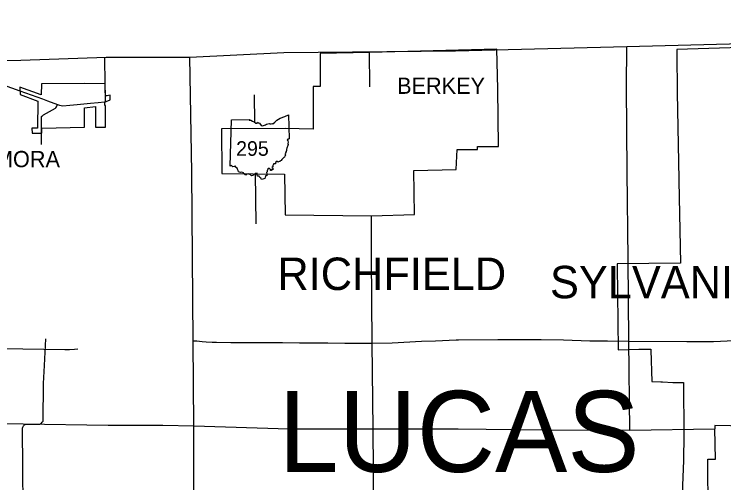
# Model space of a CAD drawing. Extents: x -232 to 448, y 619 to 1059.
# Drawn here: x 68.14 to 113.08, y 930.02 to 959.66 of the extents above; entities that cross this region are included whole.
import ezdxf

# ---------------------------------------------------------------- set-up
doc = ezdxf.new("R2010")
doc.units = 0
doc.layers.add('Default', color=7, linetype='Continuous')

msp = doc.modelspace()

# ---------------------------------------------------------------- linework, layer by layer
at = {"layer": 'Default'}
for p, q in [((73.282, 953.819), (73.282, 952.514)), ((73.923, 953.889), (73.89, 953.883)), ((73.923, 952.514), (73.923, 953.889)), ((81.816, 950.052), (81.898, 952.981)), ((81.816, 950.052), (81.898, 952.981)), ((73.282, 952.514), (73.923, 952.514))]:
    msp.add_line(p, q, dxfattribs=at)
for points in [[(191.559, 959.664), (178.631, 959.398), (164.124, 958.912), (149.104, 958.636), (143.624, 958.482), (132.12, 958.132), (126.614, 958.11), (126.592, 958.099), (122.234, 957.803), (110.103, 957.439)], [(106.941, 957.63), (115.861, 957.858), (129.538, 958.269), (129.538, 958.269), (133.907, 958.565), (133.928, 958.575), (139.422, 958.598), (145.054, 958.769)], [(79.258, 956.939), (85.208, 957.249), (96.085, 957.352), (106.941, 957.63)], [(107.118, 933.356), (107.061, 939.005), (107.011, 944.176), (106.952, 949.683), (106.905, 955.068), (106.941, 957.63)], [(87.519, 957.171), (87.518, 955.095), (87.079, 955.095), (87.068, 952.399), (85.299, 952.427), (81.27, 952.42), (81.281, 949.595), (85.266, 949.55)], [(85.303, 946.964), (90.762, 946.914), (93.491, 946.996), (93.446, 949.768), (96.124, 949.84), (96.195, 951.099), (97.484, 951.096), (97.481, 951.285), (98.815, 951.296), (98.758, 954.95), (98.7, 957.442)], [(98.7, 957.442), (90.638, 957.247), (87.519, 957.171)], [(90.668, 955.071), (90.643, 957.3)], [(110.103, 957.439), (110.104, 957.227), (110.119, 954.681)], [(46.162, 956.25), (63.186, 956.696), (68.56, 956.753), (73.967, 956.956), (79.258, 956.939)], [(73.906, 955.226), (73.886, 956.954)], [(79.515, 933.612), (79.396, 949.665), (79.258, 956.939)], [(63.784, 955.175), (63.883, 955.199), (64.007, 955.218), (64.652, 955.27), (64.823, 955.279), (65.934, 955.264), (67.19, 955.243), (67.317, 955.229), (67.375, 955.221), (67.444, 955.198), (68.507, 954.806)], [(72.566, 955.275), (69.862, 955.256), (69.851, 954.569), (68.505, 955.049)], [(68.505, 955.049), (68.508, 954.581)], [(73.884, 954.112), (73.916, 954.115), (73.969, 954.141), (74.221, 954.251), (74.224, 954.541), (74.122, 954.518), (74.02, 954.496), (73.913, 954.493), (73.906, 955.264), (72.566, 955.275)], [(73.913, 954.448), (73.91, 954.903), (73.906, 955.226)], [(68.507, 954.806), (69.922, 954.3)], [(68.508, 954.581), (69.627, 954.172), (69.622, 952.453), (69.265, 952.458), (69.271, 952.144), (69.896, 952.148), (69.891, 952.455)], [(83.387, 952.814), (83.367, 954.554)], [(110.119, 954.681), (110.225, 949.22), (110.228, 949.123), (110.343, 943.922)], [(69.922, 954.3), (70.256, 954.181), (70.882, 953.951)], [(71.661, 953.911), (72.123, 953.946), (72.973, 954.026)], [(72.973, 954.026), (73.456, 954.071), (73.863, 954.11)], [(73.863, 954.11), (73.916, 954.115), (73.913, 954.448)], [(73.89, 953.883), (73.884, 954.112)], [(69.891, 952.455), (72.584, 952.515), (72.6, 953.748), (73.282, 953.819)], [(69.898, 953.214), (69.902, 953.218), (69.989, 953.289), (70.755, 953.728), (70.786, 953.748), (70.812, 953.799), (70.882, 953.951)], [(70.882, 953.951), (71.013, 953.906), (71.119, 953.878), (71.23, 953.877), (71.661, 953.911)], [(69.875, 952.453), (69.873, 953.188), (69.898, 953.214)], [(81.898, 952.981), (83.035, 953), (83.017, 952.965), (83.124, 952.957), (83.238, 952.895), (83.335, 952.855), (83.452, 952.762), (83.523, 952.763), (83.553, 952.839), (83.607, 952.781), (83.671, 952.77), (83.782, 952.63), (83.873, 952.599), (83.983, 952.648), (84.064, 952.655), (84.124, 952.703), (84.28, 952.744), (84.324, 952.719), (84.406, 952.724), (84.448, 952.742), (84.52, 952.726), (84.647, 952.833), (84.777, 952.958), (84.978, 953.077), (85.278, 953.189), (85.515, 953.289), (85.549, 951.769)], [(81.898, 952.981), (83.035, 953), (83.017, 952.965), (83.124, 952.957), (83.238, 952.895), (83.335, 952.855), (83.452, 952.762), (83.523, 952.763), (83.553, 952.839), (83.607, 952.781), (83.671, 952.77), (83.782, 952.63), (83.873, 952.599), (83.983, 952.648), (84.064, 952.655), (84.124, 952.703), (84.28, 952.744), (84.324, 952.719), (84.406, 952.724), (84.448, 952.742), (84.52, 952.726), (84.647, 952.833), (84.777, 952.958), (84.978, 953.077), (85.278, 953.189), (85.515, 953.289), (85.549, 951.769)], [(69.878, 951.41), (69.875, 952.453)], [(85.549, 951.769), (85.514, 951.748), (85.459, 951.758), (85.423, 951.715), (85.468, 951.644), (85.489, 951.569), (85.47, 951.486), (85.489, 951.418), (85.476, 951.361), (85.442, 951.304), (85.43, 951.25), (85.401, 951.192), (85.404, 951.16), (85.376, 951.135), (85.381, 951.04), (85.367, 950.987), (85.372, 950.942), (85.327, 950.93), (85.337, 950.892), (85.309, 950.863), (85.315, 950.814), (85.282, 950.782), (85.314, 950.718), (85.288, 950.698), (85.267, 950.62), (85.21, 950.604), (85.094, 950.463), (85.053, 950.409), (85.007, 950.396), (84.982, 950.341), (84.926, 950.34), (84.841, 950.302), (84.785, 950.368), (84.689, 950.289), (84.677, 950.197), (84.555, 950.2), (84.56, 950.154), (84.533, 950.141), (84.508, 950.095), (84.522, 950.012), (84.465, 949.991), (84.472, 949.944), (84.509, 949.914), (84.525, 949.823), (84.464, 949.842), (84.414, 949.765), (84.363, 949.783), (84.38, 949.848), (84.293, 949.926), (84.211, 949.864), (84.169, 949.763), (84.168, 949.696), (84.107, 949.655), (84.146, 949.56), (84.139, 949.494), (84.14, 949.432), (84.064, 949.434), (84.018, 949.266)], [(85.549, 951.769), (85.514, 951.748), (85.459, 951.758), (85.423, 951.715), (85.468, 951.644), (85.489, 951.569), (85.47, 951.486), (85.489, 951.418), (85.476, 951.361), (85.442, 951.304), (85.43, 951.25), (85.401, 951.192), (85.404, 951.16), (85.376, 951.135), (85.381, 951.04), (85.367, 950.987), (85.372, 950.942), (85.327, 950.93), (85.337, 950.892), (85.309, 950.863), (85.315, 950.814), (85.282, 950.782), (85.314, 950.718), (85.288, 950.698), (85.267, 950.62), (85.21, 950.604), (85.094, 950.463), (85.053, 950.409), (85.007, 950.396), (84.982, 950.341), (84.926, 950.34), (84.841, 950.302), (84.785, 950.368), (84.689, 950.289), (84.677, 950.197), (84.555, 950.2), (84.56, 950.154), (84.533, 950.141), (84.508, 950.095), (84.522, 950.012), (84.465, 949.991), (84.472, 949.944), (84.509, 949.914), (84.525, 949.823), (84.464, 949.842), (84.414, 949.765), (84.363, 949.783), (84.38, 949.848), (84.293, 949.926), (84.211, 949.864), (84.169, 949.763), (84.168, 949.696), (84.107, 949.655), (84.146, 949.56), (84.139, 949.494), (84.14, 949.432), (84.064, 949.434), (84.018, 949.266)], [(84.018, 949.266), (83.885, 949.234), (83.793, 949.215), (83.761, 949.291), (83.695, 949.331), (83.652, 949.408), (83.557, 949.419), (83.535, 949.524), (83.524, 949.61), (83.395, 949.589), (83.36, 949.537), (83.314, 949.522), (83.287, 949.47), (83.225, 949.465), (83.158, 949.44), (83.114, 949.492), (83.004, 949.544), (82.955, 949.571), (82.851, 949.529), (82.829, 949.48), (82.747, 949.502), (82.728, 949.557), (82.678, 949.573), (82.667, 949.632), (82.561, 949.663), (82.479, 949.65), (82.336, 949.697), (82.327, 949.774), (82.278, 949.867), (82.253, 949.932), (82.162, 949.982), (82.144, 950.059), (82.115, 950.057), (82.088, 950.026), (81.988, 950.011), (81.947, 950.043), (81.891, 950.097), (81.816, 950.052)], [(84.018, 949.266), (83.885, 949.234), (83.793, 949.215), (83.761, 949.291), (83.695, 949.331), (83.652, 949.408), (83.557, 949.419), (83.535, 949.524), (83.524, 949.61), (83.395, 949.589), (83.36, 949.537), (83.314, 949.522), (83.287, 949.47), (83.225, 949.465), (83.158, 949.44), (83.114, 949.492), (83.004, 949.544), (82.955, 949.571), (82.851, 949.529), (82.829, 949.48), (82.747, 949.502), (82.728, 949.557), (82.678, 949.573), (82.667, 949.632), (82.561, 949.663), (82.479, 949.65), (82.336, 949.697), (82.327, 949.774), (82.278, 949.867), (82.253, 949.932), (82.162, 949.982), (82.144, 950.059), (82.115, 950.057), (82.088, 950.026), (81.988, 950.011), (81.947, 950.043), (81.891, 950.097), (81.816, 950.052)], [(83.46, 946.397), (83.424, 949.594)], [(85.266, 949.55), (85.303, 946.964)], [(90.764, 944.294), (90.762, 946.914)], [(90.991, 918.82), (91.015, 921.24), (90.986, 922.812), (90.909, 928.215), (90.864, 933.426), (90.807, 938.842), (90.764, 944.289), (90.764, 944.294)], [(110.343, 943.922), (106.33, 943.872)], [(106.33, 943.872), (106.333, 943.754), (106.389, 938.428)], [(68.668, 933.34), (68.667, 933.469), (68.686, 933.538), (68.737, 933.623), (68.791, 933.681), (68.88, 933.732), (69.755, 933.736), (69.842, 933.771), (69.921, 933.842), (69.972, 933.917), (70, 936.289), (70.052, 937.429), (70.142, 939.131)], [(79.475, 939.007), (79.713, 939.003), (80.049, 938.963), (80.292, 938.945), (80.671, 938.923), (80.943, 938.914), (81.864, 938.902), (82.238, 938.897), (83.484, 938.885), (83.757, 938.883), (84.895, 938.887), (85.12, 938.886), (86.203, 938.869), (86.464, 938.864), (87.764, 938.864), (87.996, 938.863), (89.08, 938.855), (89.369, 938.853), (89.64, 938.851), (89.914, 938.849), (90.619, 938.843), (90.807, 938.842), (92.079, 938.882), (93.93, 938.973), (94.825, 938.997), (96.122, 939.061), (96.269, 939.063)], [(96.269, 939.063), (98.756, 939.086), (100.61, 939.082), (101.512, 939.078), (102.932, 939.054), (104.596, 939.009), (105.449, 939.008), (105.719, 938.998), (107.059, 938.985), (110.73, 938.963), (112.415, 938.958), (113.741, 939.018), (113.85, 939.02)], [(47.839, 938.562), (48.772, 938.567), (49.15, 938.57), (50.258, 938.584), (51.875, 938.577), (53.435, 938.615), (54.613, 938.651), (55.518, 938.656), (55.721, 938.688), (56.005, 938.698), (57.276, 938.676), (57.825, 938.671), (59.47, 938.649), (60.673, 938.643), (62.841, 938.614), (63.431, 938.604), (65.59, 938.555), (68.68, 938.499), (71.353, 938.44), (71.641, 938.442), (71.959, 938.47), (72.174, 938.49)], [(106.389, 938.428), (107.689, 938.467), (107.715, 938.467), (107.797, 938.469), (108.339, 938.479), (108.357, 938.48), (108.454, 938.474)], [(108.454, 938.474), (108.456, 938.41), (108.521, 936.418)], [(108.521, 936.418), (109.098, 936.402), (109.19, 936.399), (109.839, 936.369), (109.901, 936.366), (110.49, 936.362), (110.522, 936.362)], [(110.522, 936.362), (110.545, 933.036), (110.544, 932.963), (110.523, 931.501), (110.519, 931.425), (110.286, 925.582)], [(131.674, 934.149), (123.263, 933.603), (115.502, 933.584), (112.51, 933.646), (112.513, 933.427)], [(46.355, 933.706), (52.547, 933.741), (63.267, 933.761), (68.715, 933.752), (74.09, 933.66), (77.553, 933.663), (79.515, 933.612)], [(68.719, 922.826), (68.719, 924.637), (68.714, 927.231), (68.699, 928.352), (68.678, 931.091), (68.668, 933.34)], [(79.52, 926.921), (79.515, 933.612)], [(79.515, 933.612), (85.524, 933.441), (90.871, 933.431), (96.246, 933.427), (101.567, 933.359), (107.118, 933.356)], [(107.118, 933.356), (112.513, 933.427)], [(112.057, 920.929), (112.055, 922.696), (112.064, 926.015), (112.087, 928.105), (112.069, 931.513), (112.553, 931.512), (112.513, 933.427)]]:
    msp.add_lwpolyline(points, dxfattribs=at)

# ---------------------------------------------------------------- texts
for s, height, p in [('BERKEY', 1.026, (92.388, 954.626)), ('295', 0.9234, (82.197, 950.705)), ('METAMORA', 1.026, (63.11, 949.986)), ('RICHFIELD', 2.052, (84.81, 942.213)), ('SYLVANIA', 2.052, (102.071, 941.691)), ('LUCAS', 5.13, (84.867, 930.703))]:
    msp.add_text(s, height=height, dxfattribs=at).set_placement(p)

doc.saveas('drawing.dxf')
